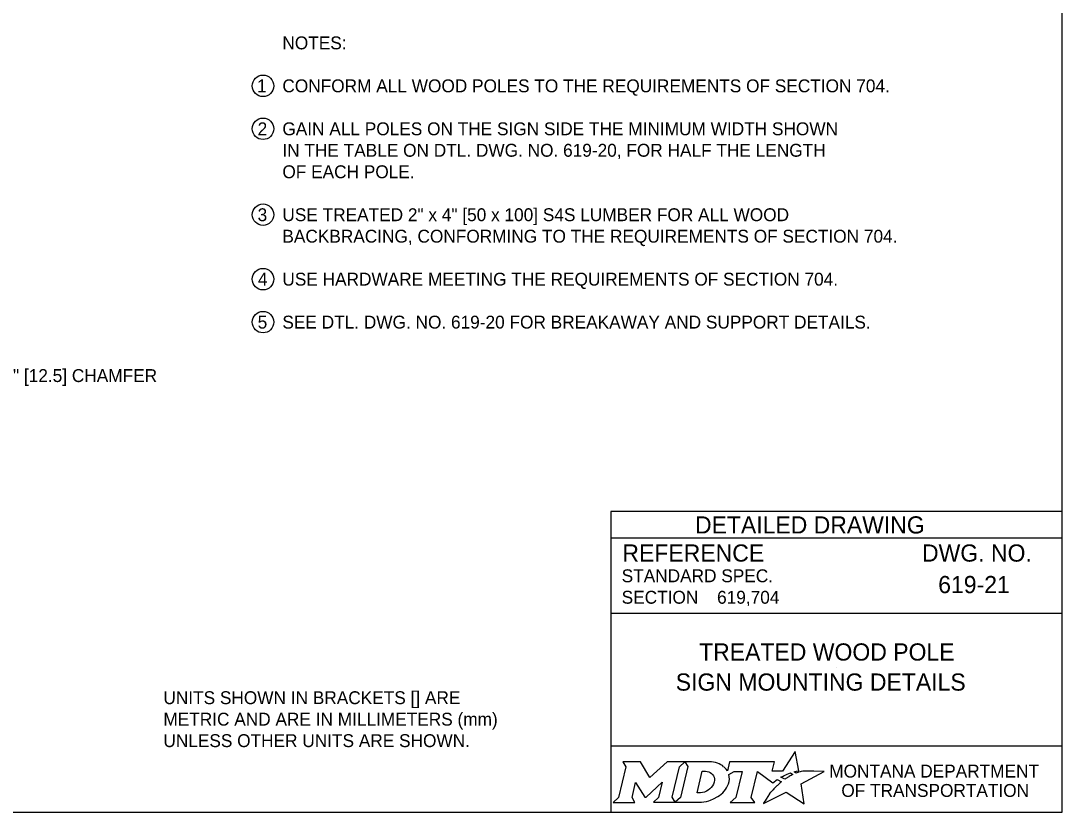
# Model space of a CAD drawing. Extents: x 49991.4 to 50021, y 49987.6 to 50011.4.
# Drawn here: x 50003.769 to 50008.615, y 50000.062 to 50003.747 of the extents above; entities that cross this region are included whole.
import ezdxf

# ---------------------------------------------------------------- set-up
doc = ezdxf.new("R2010")
doc.units = 0
doc.layers.add('Level 1', color=7, linetype='Continuous')
doc.layers.add('Level 2', color=7, linetype='Continuous')

msp = doc.modelspace()

# ---------------------------------------------------------------- linework, layer by layer
at = {"layer": 'Level 1'}
msp.add_lwpolyline([(50008.6146, 50011.2628), (50000.3356, 50011.2628), (50000.3356, 50000.0624), (50008.6146, 50000.0624)], close=True, dxfattribs=at)
at = {"layer": 'Level 2'}
for p, q in [((50008.6146, 50001.4624), (50006.5146, 50001.4624)), ((50006.5146, 50001.4624), (50006.5146, 50000.0624)), ((50008.6146, 50001.3374), (50006.5146, 50001.3374)), ((50008.2507, 50001.1223), (50008.2507, 50001.1223)), ((50007.0089, 50001.0629), (50007.0089, 50001.0629)), ((50008.6146, 50000.9874), (50006.5146, 50000.9874)), ((50007.5646, 50000.7383), (50007.5646, 50000.7383)), ((50008.6146, 50000.3693), (50006.5146, 50000.3693))]:
    msp.add_line(p, q, dxfattribs=at)
for points in [[(50007.3771, 50000.2447), (50007.3668, 50000.2503), (50007.3784, 50000.2531), (50007.39, 50000.2551), (50007.3726, 50000.3452), (50007.3131, 50000.2539), (50007.2658, 50000.2532), (50007.2761, 50000.2973), (50007.0669, 50000.2974), (50007.0568, 50000.2549), (50007.051, 50000.2632)], [(50006.5701, 50000.2974), (50006.5842, 50000.274), (50006.5507, 50000.1307), (50006.525, 50000.1082), (50006.6266, 50000.1082), (50006.6131, 50000.131), (50006.6293, 50000.2011), (50006.673, 50000.1321), (50006.6783, 50000.1321), (50006.7534, 50000.2016), (50006.737, 50000.1305), (50006.7123, 50000.1085), (50006.8139, 50000.1085), (50006.8001, 50000.1318), (50006.8333, 50000.2742)], [(50006.8333, 50000.2742), (50006.8586, 50000.2974), (50006.7762, 50000.2974), (50006.6966, 50000.2244), (50006.6521, 50000.2971), (50006.5701, 50000.2974)], [(50006.9722, 50000.2974), (50006.8586, 50000.2974), (50006.8733, 50000.2745), (50006.8394, 50000.1307), (50006.8139, 50000.1085), (50006.9245, 50000.1085)], [(50006.9962, 50000.2107), (50006.995, 50000.2026), (50006.9918, 50000.1933), (50006.9876, 50000.1851), (50006.982, 50000.1776), (50006.9755, 50000.1707), (50006.9676, 50000.1644), (50006.9593, 50000.1597), (50006.9502, 50000.1558), (50006.9411, 50000.1535), (50006.9319, 50000.1526), (50006.916, 50000.1526), (50006.9396, 50000.2526), (50006.9556, 50000.2526), (50006.9632, 50000.252), (50006.9708, 50000.2501), (50006.9774, 50000.2471), (50006.9835, 50000.2429), (50006.9883, 50000.2379), (50006.992, 50000.2319), (50006.9947, 50000.2257), (50006.9963, 50000.2183), (50006.9963, 50000.2153), (50006.9962, 50000.2107)], [(50007.0636, 50000.2383), (50007.0882, 50000.2514), (50007.1251, 50000.2514), (50007.0965, 50000.1309), (50007.069, 50000.1082), (50007.1852, 50000.1082), (50007.1682, 50000.1311), (50007.1964, 50000.2513), (50007.2677, 50000.1996), (50007.2888, 50000.2147), (50007.3085, 50000.2038)], [(50007.2527, 50000.1479), (50007.2374, 50000.1235), (50007.2327, 50000.116), (50007.2269, 50000.1074), (50007.2246, 50000.1031), (50007.3299, 50000.1562), (50007.4138, 50000.1011), (50007.4007, 50000.1938), (50007.5076, 50000.2522), (50007.4583, 50000.253), (50007.4282, 50000.2534), (50007.4074, 50000.2537), (50007.4006, 50000.2522), (50007.3957, 50000.251), (50007.3873, 50000.2487), (50007.3771, 50000.2447)], [(50007.3267, 50000.2171), (50007.3243, 50000.2154), (50007.306, 50000.225), (50007.3163, 50000.2307), (50007.3204, 50000.2329), (50007.329, 50000.2369), (50007.3347, 50000.2395), (50007.3426, 50000.2425), (50007.3499, 50000.2452), (50007.3617, 50000.2378), (50007.3577, 50000.2357), (50007.3531, 50000.2332), (50007.3489, 50000.231), (50007.3439, 50000.2281), (50007.342, 50000.227), (50007.3393, 50000.2254), (50007.3368, 50000.224), (50007.3345, 50000.2224), (50007.3319, 50000.2206), (50007.3292, 50000.2188), (50007.3267, 50000.2171)], [(50007.2666, 50000.164), (50007.2666, 50000.164)], [(50006.9702, 50000.1158), (50006.9786, 50000.1184), (50006.9916, 50000.1238), (50007.012, 50000.1348)]]:
    msp.add_lwpolyline(points, dxfattribs=at)
for centre in [(50004.8962, 50003.444), (50004.8962, 50003.244), (50004.8962, 50002.844), (50004.8962, 50002.544), (50004.8962, 50002.344)]:
    msp.add_circle(centre, 0.05, dxfattribs=at)
for centre, radius, start, end in [((50006.9953, 50000.219), 0.0709, 339.5329, 15.8582), ((50006.9513, 50000.2363), 0.1183, 300.9103, 339.1383)]:
    msp.add_arc(centre, radius, start, end, dxfattribs=at)
for centre, major_axis, ratio, start_param, end_param in [((50006.9701, 50000.25), (0.0834, -0.0037), 0.568097, 0.61298, 1.570796), ((50007.0257, 50000.2573), (0.0361, -0.0295), 0.469099, 1.225588, 1.570796), ((50007.2974, 50000.1941), (-0.0112, -0.0097), 0.021651, 3.157348, 6.283185), ((50007.2597, 50000.1559), (-0.00694, -0.00806), 0.008222, 0, 3.137361), ((50007.2764, 50000.1742), (-0.0098, -0.0102), 0.016458, 3.141593, 6.279097), ((50006.9248, 50000.2568), (0, 0.1484), 0.987302, 3.139398, 3.456847)]:
    msp.add_ellipse(centre, major_axis=major_axis, ratio=ratio, start_param=start_param, end_param=end_param, dxfattribs=at)

# ---------------------------------------------------------------- texts
for s, height, p in [('NOTES:', 0.06, (50004.9862, 50003.614)), ('1', 0.06, (50004.8681, 50003.414)), ('CONFORM ALL WOOD POLES TO THE REQUIREMENTS OF SECTION 704.', 0.06, (50004.9862, 50003.414)), ('2', 0.06, (50004.871, 50003.214)), ('GAIN ALL POLES ON THE SIGN SIDE THE MINIMUM WIDTH SHOWN', 0.06, (50004.9862, 50003.214)), ('IN THE TABLE ON DTL. DWG. NO. 619-20, FOR HALF THE LENGTH', 0.06, (50004.9862, 50003.114)), ('OF EACH POLE.', 0.06, (50004.9862, 50003.014)), ('3', 0.06, (50004.871, 50002.814)), ('USE TREATED 2" x 4" [50 x 100] S4S LUMBER FOR ALL WOOD ', 0.06, (50004.9862, 50002.814)), ('BACKBRACING, CONFORMING TO THE REQUIREMENTS OF SECTION 704. ', 0.06, (50004.9862, 50002.714)), ('4', 0.06, (50004.8722, 50002.514)), ('USE HARDWARE MEETING THE REQUIREMENTS OF SECTION 704.', 0.06, (50004.9862, 50002.514)), ('5', 0.06, (50004.8713, 50002.314)), ('SEE DTL. DWG. NO. 619-20 FOR BREAKAWAY AND SUPPORT DETAILS.', 0.06, (50004.9862, 50002.314)), ('1/2" [12.5] CHAMFER', 0.06, (50003.6213, 50002.0651)), ('DETAILED DRAWING', 0.0799, (50006.9063, 50001.3599)), ('REFERENCE', 0.08, (50006.5682, 50001.229)), ('DWG. NO.', 0.08, (50007.9624, 50001.229)), ('STANDARD SPEC.', 0.06, (50006.5649, 50001.133)), ('619-21', 0.08, (50008.0378, 50001.0823)), ('SECTION', 0.06, (50006.5649, 50001.033)), ('619,704', 0.06, (50007.0089, 50001.0329)), ('TREATED WOOD POLE', 0.08, (50006.9252, 50000.7683)), ('SIGN MOUNTING DETAILS', 0.08, (50006.8165, 50000.6283)), ('UNITS SHOWN IN BRACKETS [] ARE ', 0.06, (50004.4325, 50000.5654)), ('METRIC AND ARE IN MILLIMETERS (mm) ', 0.06, (50004.4325, 50000.4654)), ('UNLESS OTHER UNITS ARE SHOWN.', 0.06, (50004.4325, 50000.3654)), ('MONTANA DEPARTMENT', 0.06, (50007.5308, 50000.2236)), ('OF TRANSPORTATION', 0.06, (50007.587, 50000.1336))]:
    msp.add_text(s, height=height, dxfattribs=at).set_placement(p)

doc.saveas('drawing.dxf')
